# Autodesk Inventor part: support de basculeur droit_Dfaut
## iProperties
Created: 2006-03
Part Number: support de basculeur droit_Dfaut
Document SubType Name: Modeling
Designer: Flavien MARTY
Author: Flavien MARTY
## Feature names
1. Base1
